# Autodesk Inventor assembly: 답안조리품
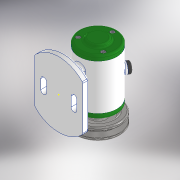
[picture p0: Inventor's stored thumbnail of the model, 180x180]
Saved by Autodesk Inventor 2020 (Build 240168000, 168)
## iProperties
Created: 2022-02
Part Number: 답안조리품
Document SubType Name: Assembly
Designer: 602-01
Author: 602-01
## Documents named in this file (14)
- C:\Users\602-01\Desktop\720206V1022\답안조리품.iam
- C:\Users\602-01\Desktop\720206V1022\본체.ipt
- C:\Users\602-01\Desktop\720206V1022\베어링 6002.ipt
- C:\Users\602-01\Desktop\720206V1022\앞커버.ipt
- C:\Users\602-01\Desktop\720206V1022\뒤커버.ipt
- C:\Users\602-01\Desktop\720206V1022\오일 실 15 x 25 x 7.ipt
- C:\Users\602-01\Desktop\720206V1022\축.ipt
- C:\Users\602-01\Desktop\720206V1022\키 3 x 3 x 12.ipt
- C:\Users\602-01\Desktop\720206V1022\V벨트풀리.ipt
- C:\Users\602-01\Desktop\720206V1022\평와셔 8 x 17.ipt
- C:\Users\602-01\Desktop\720206V1022\스프링와셔 8.ipt
- C:\Users\602-01\Desktop\720206V1022\너트 M8.ipt
- C:\Users\602-01\Desktop\720206V1022\고무 캡.ipt
- C:\Users\602-01\Desktop\720206V1022\볼트 M4 x 10.ipt
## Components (2 placed, 2 different names)
1. V벨트풀리:1
2. 고무 캡:1 — 각도:1
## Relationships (1: Angle 1)
- 각도:1 [Angle]: 고무 캡:1
